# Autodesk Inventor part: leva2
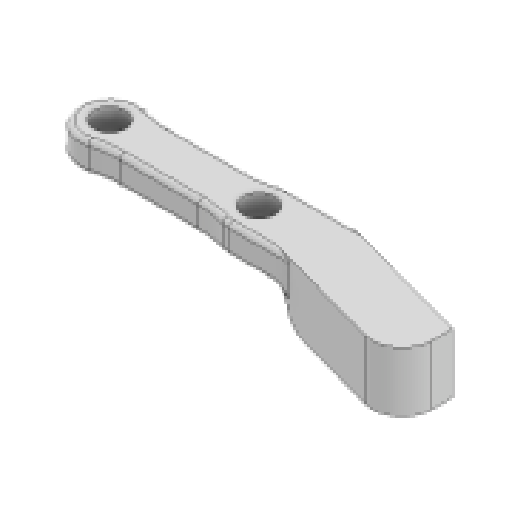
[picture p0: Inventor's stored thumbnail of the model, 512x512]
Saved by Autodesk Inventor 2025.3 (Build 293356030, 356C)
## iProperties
Created: 2026-03
Part Number: leva2
Material: Generico
Document SubType Name: Modeling
Designer: R5800u
Density: 1 g/cm^3
Appearance: Default
Author: R5800u
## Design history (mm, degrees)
sketch "Schizzo1"
  geometry: L1 (7.5, 2.5)-(-7.5, 2.5); L2 (-7.5, 2.5)-(-7.5, -2.5); L3 (-7.5, -2.5)-(7.5, -2.5); L4 (7.5, -2.5)-(7.5, 2.5); L5 (7.5, 2.5)-(-7.5, -2.5); L6 (-7.5, 2.5)-(7.5, -2.5); C1 r 3 at (7.5, 0); C2 r 3 at (-7.5, 0); 5 further points
  constraints: 12 end point, 4 midpoint, 2 centre point, 2 parallel, 1 horizontal, 1 perpendicular
  dimensions: "d0" = 15 distance of L3.end L2.end; "d1" = 5 distance of L2.end L1.end; "d4" = 6 diameter of C1; "d5" = 6 diameter of C2
extrude "Estrusione1" new body sketch "Schizzo1" distance "d2" = 3; taper "d3" = 0 deg
sketch "Schizzo2"
  geometry: A1 r 3 centre (7.5, 0) between (5.842, -2.5) and (5.842, 2.5) reference; A2 r 3 centre (-7.5, 0) between (-5.842, 2.5) and (-5.842, -2.5) reference; 3 further points
  constraints: 2 coincident
hole "Foro1" sketch "Schizzo2" at (7.5, 0), (-7.5, 0) diameter "d6" = 3.2; stored, may be unused: countersink angle "d10" = 90 deg, drill point angle "d12" = 118 deg; dims "d7" = 6, "d8" = 6.5, "d9" = 3.4, "d11" = 8
sketch "Schizzo3"
  geometry: L1 (5.842, 2.5)-(-5.842, 2.5) reference; L2 (-5.842, -2.5)-(5.842, -2.5) reference; L3 (7.5, 0)-(7.5, 3); L4 (7.5, 0)-(7.5, -3); L5 (7.5, 3)-(13.5, 3); L6 (13.5, 3)-(13.5, -3); L7 (13.5, -3)-(7.5, -3); L8 (7.5, -3)-(7.5, 3); L9 (13.5, -3)-(10.036, 3); C1 r 1.6 at (-7.5, 0) reference; C2 r 1.6 at (7.5, 0) reference; A1 r 3 centre (7.5, 0) between (5.842, -2.5) and (5.842, 2.5) reference; A2 r 3 centre (-7.5, 0) between (-5.842, 2.5) and (-5.842, -2.5) reference; 2 further points
  constraints: 14 end point, 3 point on line, 2 parallel, 2 point on circle, 1 horizontal, 1 perpendicular, 1 vertical
  dimensions: "d13" = 6 distance of L6.end L7.end; "d16" = 30 deg angle of L9 L6
extrude "Estrusione2" join sketch "Schizzo3" stored distance "d14" = 10; taper "d15" = 0 deg
fillet "Raccordo1" dims "d17" = 10
sketch "Schizzo5"
  geometry: L1 (13.5, -3)-(13.5, 3) reference; L2 (13.5, -3)-(16.5, 2.196); L3 (16.5, 2.196)-(13.5, 3); L4 (13.5, 3)-(16.098, 1.5); 1 further point
  constraints: 6 end point, 1 perpendicular, 1 point on line
  dimensions: "d22" = 6 distance of L1.start L2.end; "d23" = 30 deg angle of L1 L2
extrude "Estrusione4" join sketch "Schizzo5" stored distance "d24" = 10; taper "d25" = 0 deg
sketch "Schizzo6"
  geometry: L1 (13.5, -3)-(13.5, 3) reference; L2 (13.5, 3)-(27.964, -0.973); L3 (27.964, -0.973)-(27.964, -6.973); L4 (27.964, -6.973)-(13.5, -3); L5 (27.964, -3.973)-(13.5, 0); 1 further point
  constraints: 8 end point, 2 midpoint, 1 parallel
  dimensions: "d26" = 6 distance of L2.end L3.end; "d27" = 74.64 deg angle of L1 L2; "d33" = 15 distance of L5.start L5.end
extrude "Estrusione5" join sketch "Schizzo6" distance "d28" = 10; taper "d29" = 0 deg
chamfer "Smusso1" distance "d30" = 2; stored, may be unused: second distance "d31" = 2, angle "d32" = 45 deg
fillet "Raccordo2" dims "d34" = 2
fillet "Raccordo3" dims "d35" = 3
fillet "Raccordo4" dims "d36" = 0.53
fillet "Raccordo5" dims "d37" = 0.5
node "Solido1"
node "Linea chiusa proiettata1"
